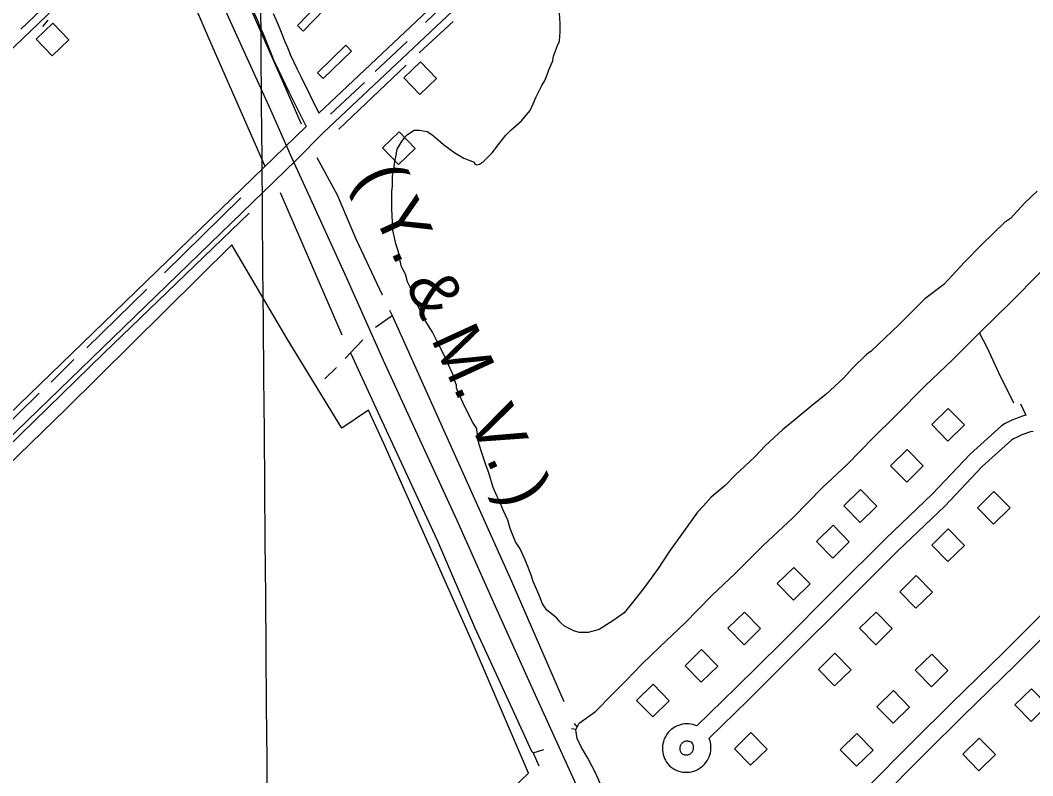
# Model space of a CAD drawing. Extents: x 3568792 to 3606828, y 529143 to 554785.
# Drawn here: x 3581187 to 3582938, y 537149 to 538456 of the extents above; entities that cross this region are included whole.
import ezdxf

# ---------------------------------------------------------------- set-up
doc = ezdxf.new("R2010")
doc.units = 0
for name, color, linetype in [('V-BLDG-OTLN', 7, 'Continuous'), ('V-DTCH-CNTR', 7, 'Continuous'), ('V-GRID-MAJR', 7, 'Continuous'), ('V-RAIL-IDEN', 7, 'Continuous'), ('V-RAIL-TRAK', 7, 'Continuous'), ('V-ROAD-CNTR', 7, 'Continuous'), ('V-SITE-VEGE', 7, 'Continuous'), ('V-TOPO-SHOR', 7, 'Continuous')]:
    doc.layers.add(name, color=color, linetype=linetype)

msp = doc.modelspace()

# ---------------------------------------------------------------- linework, layer by layer
at = {"layer": 'V-BLDG-OTLN'}
for points in [[(3581731, 538494.1), (3581720.9, 538503.9), (3581666.1, 538447.3), (3581676.1, 538437.5)], [(3581243.4, 538451.1), (3581214.4, 538423.5), (3581242.1, 538394.5), (3581271, 538422.1)], [(3581759.6, 538402.8), (3581749.9, 538412.9), (3581700.8, 538365.4), (3581710.5, 538355.3)], [(3581879.2, 538384.3), (3581850.4, 538356.6), (3581878.1, 538327.8), (3581906.9, 538355.5)], [(3581842.3, 538263), (3581813.4, 538235.3), (3581841.2, 538206.4), (3581870, 538234.2)], [(3582791.8, 537784.6), (3582763.2, 537756.6), (3582791.2, 537728), (3582819.8, 537756)], [(3582720.7, 537713.4), (3582692.1, 537685.4), (3582720.1, 537656.9), (3582748.7, 537684.9)], [(3582640.1, 537643.9), (3582611.5, 537615.9), (3582639.5, 537587.3), (3582668.1, 537615.3)], [(3582870.8, 537640.7), (3582842.3, 537612.7), (3582870.3, 537584.2), (3582898.8, 537612.2)], [(3582592.7, 537582.2), (3582564.1, 537554.2), (3582592.1, 537525.6), (3582620.7, 537553.6)], [(3582791.8, 537576), (3582763.2, 537548), (3582791.2, 537519.4), (3582819.8, 537547.4)], [(3582524.8, 537509.5), (3582496.2, 537481.5), (3582524.2, 537452.9), (3582552.8, 537480.9)], [(3582736.5, 537495.4), (3582707.9, 537467.4), (3582735.9, 537438.8), (3582764.5, 537466.8)], [(3582439.4, 537432.1), (3582410.9, 537404.1), (3582438.9, 537375.5), (3582467.4, 537403.5)], [(3582667, 537432.1), (3582638.4, 537404.1), (3582666.4, 537375.5), (3582695, 537403.5)], [(3582365.2, 537367.3), (3582336.6, 537339.3), (3582364.6, 537310.7), (3582393.2, 537338.7)], [(3582595.9, 537361), (3582567.3, 537333), (3582595.3, 537304.4), (3582623.9, 537332.4)], [(3582763.4, 537359.4), (3582734.8, 537331.4), (3582762.8, 537302.8), (3582791.4, 537330.8)], [(3582281.4, 537307.2), (3582252.8, 537279.2), (3582280.8, 537250.7), (3582309.4, 537278.7)], [(3582697, 537296.2), (3582668.4, 537268.2), (3582696.4, 537239.6), (3582725, 537267.6)], [(3582935.6, 537299.3), (3582907.1, 537271.3), (3582935.1, 537242.8), (3582963.6, 537270.8)], [(3582450.5, 537223.5), (3582421.9, 537195.5), (3582449.9, 537166.9), (3582478.5, 537194.9)], [(3582633.8, 537221.9), (3582605.2, 537193.9), (3582633.2, 537165.3), (3582661.8, 537193.3)], [(3582845.6, 537214), (3582817, 537186), (3582845, 537157.4), (3582873.6, 537185.4)]]:
    msp.add_lwpolyline(points, close=True, dxfattribs=at)
at = {"layer": 'V-DTCH-CNTR'}
for points in [[(3581743, 537750.6), (3581648.6, 537905.1), (3581552.6, 538067.7), (3581265.5, 537783.1), (3580939.5, 537466.5), (3580616.5, 537161.8), (3580274.6, 536830.3), (3580101.1, 536657.5), (3580153.1, 536594.7), (3580038.4, 536485.8), (3579962.5, 536549.1), (3579802, 536396.8), (3579619.1, 536225.5), (3579445.1, 536055.2), (3579345.4, 535955.3), (3579344.6, 535829.1)], [(3580720, 535828.9), (3580973.2, 536069.6), (3581210.5, 536310.3), (3581461.7, 536563.9), (3581688, 536784.7), (3581968.1, 537059.3), (3582065.8, 537153.2), (3581966.8, 537384.6), (3581815.9, 537723.7), (3581788.9, 537781.5), (3581743, 537750.6)]]:
    msp.add_lwpolyline(points, dxfattribs=at)
at = {"layer": 'V-GRID-MAJR'}
msp.add_spline([(3581635.7, 534620.4), (3581585.4, 540678.1), (3581535.2, 546738.9), (3581484.9, 552799.7), (3581484.9, 552802.8)], degree=3, dxfattribs=at)
at = {"layer": 'V-RAIL-TRAK'}
msp.add_lwpolyline([(3581410.4, 538763.3), (3581480.1, 538611.3), (3581541.1, 538473.8), (3581619.4, 538300.9), (3581656.8, 538217.8), (3581679.1, 538168.4), (3581751, 538010.4), (3581814.7, 537867.9), (3581883.5, 537717.3), (3581941.8, 537591), (3582005.6, 537448.5), (3582071.6, 537301.5), (3582148, 537134.5)], dxfattribs=at)
at = {"layer": 'V-ROAD-CNTR'}
msp.add_line((3580917.4, 537532.7), (3581681.3, 538272.3), dxfattribs=at)
for points in [[(3580938.2, 537511.2), (3581663.4, 538213.2), (3581711.4, 538262), (3582051.3, 538582.5), (3582436.7, 538953.5), (3582639.8, 539148.6), (3582821.3, 539321.6), (3582927.1, 539429.2)], [(3581703, 538295.3), (3582030.7, 538604.3), (3582415.9, 538975.1), (3582608.4, 539160.1)], [(3581303.8, 539100.6), (3581375.6, 538947), (3581461.2, 538756.9), (3581597, 538455.6)], [(3581328.7, 538556.4), (3581178.3, 538412), (3580914.7, 538160.5)], [(3581624.4, 538467.7), (3581629.4, 538456.1), (3581634.4, 538444.4), (3581639.3, 538432.6), (3581644.1, 538420.8), (3581648.9, 538409), (3581653.5, 538397.3)], [(3581596.9, 538455.8), (3581601.9, 538444.3), (3581606.8, 538432.7), (3581611.6, 538421.2), (3581616.3, 538409.6), (3581621, 538397.9), (3581625.6, 538386.3)], [(3581653.1, 538398.2), (3581659.3, 538385), (3581665.6, 538371.8), (3581671.9, 538358.7), (3581703, 538295.3)], [(3581626, 538385.4), (3581632.2, 538372.1), (3581638.6, 538358.9), (3581645, 538345.6), (3581651.4, 538332.4), (3581681.3, 538272.3)], [(3582916.7, 537792.7), (3582925.8, 537772.7)], [(3582925.9, 537772.6), (3582920.1, 537770.9), (3582914, 537768.8), (3582908, 537766.5), (3582902.1, 537764), (3582896.3, 537761.3), (3582890.6, 537758.3), (3582883.9, 537754.5), (3582829.6, 537705.2), (3582764.7, 537636.6), (3582683.8, 537559.6), (3582595, 537471), (3582503.2, 537379.1), (3582424.5, 537300.8), (3582357.2, 537235.3)], [(3582938.5, 537744.8), (3582934.1, 537743.7), (3582929.1, 537742.2), (3582924.1, 537740.6), (3582919.2, 537738.7), (3582914.4, 537736.7), (3582909.7, 537734.4), (3582905, 537732), (3582901.6, 537730.1), (3582850.6, 537683.7), (3582786, 537615.4), (3582704.8, 537538.1), (3582616.2, 537449.8), (3582524.3, 537357.9), (3582445.6, 537279.4), (3582378.2, 537214)], [(3582648.6, 537125.7), (3582730.9, 537208.4), (3582797.3, 537274.5), (3582886.7, 537361.4), (3582977.8, 537452.8), (3582990.9, 537466), (3582995.3, 537469.8), (3582999.8, 537473.2), (3583004.4, 537476.5), (3583009.1, 537479.5), (3583014, 537482.2), (3583019.1, 537484.7), (3583024.2, 537487), (3583029.4, 537489), (3583051, 537496.2)], [(3582669.9, 537104.6), (3582752.1, 537187.2), (3582818.4, 537253.2), (3582907.8, 537340), (3582999, 537431.6), (3583011.4, 537444), (3583014.4, 537446.6), (3583017.6, 537449.1), (3583021, 537451.5), (3583024.5, 537453.7), (3583028.1, 537455.7), (3583031.8, 537457.6), (3583035.6, 537459.2), (3583039.5, 537460.7), (3583063.3, 537468.7)], [(3582357.2, 537235.3), (3582353.8, 537236.6), (3582350.3, 537237.6), (3582346.7, 537238.3), (3582343.1, 537238.7), (3582339.4, 537238.8), (3582335.8, 537238.6), (3582332.2, 537238), (3582328.6, 537237.2), (3582325.2, 537236), (3582321.8, 537234.6), (3582318.6, 537232.9), (3582315.5, 537230.9), (3582312.6, 537228.7), (3582309.9, 537226.2), (3582307.5, 537223.5), (3582305.3, 537220.6), (3582303.3, 537217.5), (3582301.6, 537214.3), (3582300.2, 537210.9), (3582299.1, 537207.4), (3582298.2, 537203.9), (3582297.7, 537200.3), (3582297.5, 537196.6), (3582297.6, 537193), (3582298, 537189.3), (3582298.7, 537185.8), (3582299.8, 537182.3), (3582301.1, 537178.9), (3582302.7, 537175.6), (3582304.6, 537172.4), (3582306.7, 537169.5), (3582309.5, 537166.2), (3582312.9, 537163.5), (3582316, 537161.4), (3582319.2, 537159.5), (3582322.6, 537158), (3582326.1, 537156.7), (3582329.7, 537155.8), (3582333.3, 537155.2), (3582337.1, 537154.9), (3582340.8, 537154.9), (3582344.5, 537155.3), (3582348.1, 537155.9), (3582351.7, 537156.9), (3582355.2, 537158.2), (3582358.6, 537159.8), (3582361.8, 537161.7), (3582364.8, 537163.8), (3582367.7, 537166.2), (3582370.3, 537168.9), (3582372.7, 537171.7), (3582374.8, 537174.8), (3582376.6, 537178), (3582378.2, 537181.4), (3582379.5, 537184.8), (3582380.4, 537188.4), (3582381.1, 537192.1), (3582381.4, 537195.8), (3582381.4, 537199.5), (3582381.1, 537203.2), (3582380.4, 537206.9), (3582379.5, 537210.5), (3582378.2, 537214)], [(3582349.5, 537205), (3582348.2, 537206.1), (3582347.3, 537206.7), (3582346.3, 537207.3), (3582345.4, 537207.8), (3582344.3, 537208.1), (3582343.3, 537208.4), (3582342.2, 537208.6), (3582341.1, 537208.8), (3582340.1, 537208.8), (3582339, 537208.7), (3582337.9, 537208.6), (3582336.8, 537208.3), (3582335.8, 537208), (3582334.8, 537207.5), (3582333.8, 537207), (3582332.9, 537206.4), (3582332, 537205.8), (3582331.2, 537205), (3582330.5, 537204.2), (3582329.8, 537203.4), (3582329.3, 537202.4), (3582328.8, 537201.5), (3582328.3, 537200.5), (3582328, 537199.4), (3582327.7, 537198.4), (3582327.6, 537197.3), (3582327.5, 537196.2), (3582327.6, 537195.1), (3582327.7, 537194), (3582327.9, 537193), (3582328.2, 537191.9), (3582328.6, 537190.9), (3582329.1, 537189.9), (3582329.6, 537189), (3582330.3, 537188.1), (3582330.6, 537187.8), (3582330.9, 537187.5), (3582331.8, 537186.8), (3582332.8, 537186.3), (3582333.8, 537185.8), (3582334.9, 537185.5), (3582336, 537185.2), (3582337, 537185), (3582338.2, 537184.9), (3582339.3, 537184.9), (3582340.4, 537185), (3582341.5, 537185.2), (3582342.5, 537185.5), (3582343.6, 537185.9), (3582344.6, 537186.4), (3582345.5, 537186.9), (3582346.4, 537187.6), (3582347.3, 537188.3), (3582348.1, 537189.1), (3582348.8, 537189.9), (3582349.4, 537190.8), (3582350, 537191.8), (3582350.4, 537192.8), (3582350.8, 537193.9), (3582351.1, 537194.9), (3582351.3, 537196), (3582351.4, 537197.1), (3582351.4, 537198.2), (3582351.3, 537199.3), (3582351.1, 537200.4), (3582350.8, 537201.5), (3582350.5, 537202.6), (3582350, 537203.6), (3582349.4, 537204.5), (3582348.8, 537205.4), (3582347.7, 537206.8)]]:
    msp.add_lwpolyline(points, dxfattribs=at)
at = {"layer": 'V-SITE-VEGE'}
for points in [[(3581980.1, 537723.8), (3581976.7, 537747.6), (3581976.7, 537749.8), (3581969.9, 537760), (3581954, 537790.6), (3581948.4, 537804.2), (3581942.7, 537816.6), (3581941.6, 537820), (3581941.6, 537824.6), (3581938.2, 537832.5), (3581934.8, 537843.8), (3581925.7, 537863.1), (3581919, 537878.9), (3581907.6, 537901.6), (3581899.7, 537916.3), (3581887.3, 537936.7), (3581871.4, 537968.4), (3581868, 537978.6), (3581861.2, 537994.4), (3581856.7, 538003.5), (3581853.3, 538017), (3581846.5, 538029.5), (3581842, 538047.6), (3581840.9, 538055.5), (3581836.3, 538069.1), (3581834.1, 538080.5), (3581830.7, 538095.2), (3581830.7, 538106.5), (3581829.5, 538129.1), (3581829.5, 538159.7), (3581830.7, 538169.9), (3581830.7, 538186.9), (3581832.9, 538195.9), (3581834.1, 538208.4), (3581836.3, 538219.7), (3581838.6, 538233.3), (3581845.4, 538244.6), (3581852.2, 538253.7), (3581856.7, 538258.2), (3581868.1, 538266.1), (3581877.1, 538266.1), (3581890.7, 538263.9), (3581898.6, 538258.2), (3581909.9, 538249.1), (3581919, 538241.2), (3581938.2, 538226.5), (3581954.1, 538217.4), (3581972.2, 538210.6), (3581973.3, 538207.2), (3581976.7, 538206.1), (3581981.3, 538207.2), (3581988.1, 538211.8), (3582002.8, 538226.5), (3582014.1, 538241.2), (3582026.6, 538257.1), (3582035.6, 538266.1), (3582053.7, 538282), (3582061.7, 538292.2), (3582068.5, 538300.1), (3582074.1, 538311.4), (3582078.7, 538322.7), (3582088.8, 538343.1), (3582093.4, 538351), (3582096.8, 538359), (3582101.3, 538370.3), (3582108.1, 538386.1), (3582109.2, 538394), (3582116, 538412.2), (3582119.4, 538420.1), (3582120.6, 538435.9), (3582120.6, 538450.7), (3582119.4, 538468.8)], [(3582945.9, 538160.7), (3582924.4, 538140.3), (3582899.5, 538113.2), (3582889.3, 538106.4), (3582849.7, 538067.9), (3582820.2, 538037.3), (3582784, 537998.8), (3582751.2, 537973.9), (3582707, 537929.8), (3582658.3, 537883.3), (3582650.4, 537877.7), (3582626.6, 537855), (3582610.7, 537836.9), (3582580.2, 537808.6), (3582557.5, 537790.5), (3582526.9, 537765.6), (3582505.4, 537747.5), (3582476, 537720.3), (3582456.7, 537699.9), (3582423.9, 537669.4), (3582405.8, 537651.3), (3582382, 537630.9), (3582368.4, 537616.2), (3582358.2, 537604.9), (3582308.4, 537535.8), (3582290.3, 537507.5), (3582265.4, 537473.5), (3582250.6, 537454.3), (3582231.4, 537430.5), (3582213.3, 537418.1), (3582188.4, 537402.2), (3582169.1, 537396.5), (3582153.3, 537396.6), (3582144.2, 537399.9), (3582128.4, 537407.9), (3582120.4, 537414.7), (3582114.8, 537421.5), (3582108, 537427.1), (3582097.8, 537435.1), (3582089.9, 537446.4), (3582084.2, 537461.1), (3582074, 537484.9), (3582070.6, 537496.2), (3582065, 537510.9), (3582060.4, 537522.2), (3582051.4, 537541.5), (3582043.5, 537553.9), (3582034.4, 537576.6), (3582029.9, 537591.3), (3582022, 537608.3), (3582016.3, 537623), (3582011.8, 537632.1), (3582005, 537647.9), (3581997.1, 537672.8), (3581992.5, 537685.3), (3581985.7, 537705.7), (3581980.1, 537723.8)]]:
    msp.add_lwpolyline(points, dxfattribs=at)
at = {"layer": 'V-TOPO-SHOR'}
for p, q in [((3581187.8, 538441), (3581255.7, 538505.7)), ((3581945.4, 538508.3), (3581888, 538452.3)), ((3581225.9, 538445.1), (3581235.4, 538456.1)), ((3581876.6, 538399.9), (3581935.4, 538454.1)), ((3581856.1, 538419.5), (3581800.5, 538367.6)), ((3581737.7, 538267.9), (3581854.3, 538378.5)), ((3581782.3, 538348.5), (3581723.5, 538293.8)), ((3581436.4, 538018.9), (3581568.4, 538148.6)), ((3581743.4, 537911.1), (3581636.7, 538157.8)), ((3581302, 537889.6), (3581405.6, 537990.9)), ((3581801.5, 537925.2), (3581830, 537945.2)), ((3581240.1, 537830), (3581279.5, 537869)), ((3581713.5, 537835.4), (3581733.7, 537855.1)), ((3582144.7, 537239.2), (3582150, 537232.9)), ((3582140.5, 537230.4), (3582148.3, 537229.5)), ((3582074.1, 537188.3), (3582083.8, 537165.9))]:
    msp.add_line(p, q, dxfattribs=at)
for points in [[(3581317.4, 539072.2), (3581339, 539024.4), (3581374, 538947.2), (3581427.7, 538828.1), (3581455.5, 538764.3), (3581479.2, 538709.9), (3581527, 538609.6), (3581531.4, 538599.7), (3581576.6, 538496.5), (3581634.1, 538365), (3581672.7, 538277.2)], [(3581610.7, 538202.9), (3581516.3, 538417), (3581455.3, 538559.4)], [(3581699.8, 538218.8), (3581734.7, 538154), (3581767.4, 538078.1), (3581812.9, 537981.1)], [(3580510, 537087.1), (3580799.8, 537368.5), (3581064.9, 537620.6), (3581331.3, 537880), (3581582.5, 538122.1)], [(3582201.7, 537107.6), (3582182.4, 537152.5), (3582168.3, 537179.5), (3582157.6, 537197.8), (3582150, 537213.6), (3582147.9, 537228.6), (3582153.6, 537240), (3582181.5, 537260), (3582211.1, 537289.8), (3582235.1, 537313.4), (3582261.6, 537341.3), (3582293.2, 537372.2), (3582336, 537412.9), (3582382.9, 537460.9), (3582423.3, 537498.8), (3582471.4, 537546.8), (3582523.4, 537595.9), (3582574.2, 537647.4), (3582617, 537687.7), (3582661.9, 537733.4), (3582700.3, 537771.3), (3582752.4, 537824), (3582799.2, 537868.4), (3582846.1, 537915.3), (3582899.7, 537967.5), (3582951, 538019.4)], [(3581825.7, 537954.7), (3581830, 537945.2), (3582036.7, 537485.7), (3582127.2, 537277.4)], [(3582905.5, 537793.5), (3582879.4, 537846), (3582859.5, 537889), (3582846.1, 537915.3)], [(3581748.8, 537871.1), (3581757.8, 537880.6), (3581779.5, 537903.2)], [(3581757.8, 537880.6), (3581808.7, 537770.6), (3581908.2, 537556.4), (3581972.3, 537406.1), (3582037.9, 537264.4), (3582071.3, 537191.5), (3582074.1, 537188.3), (3582092.4, 537194.2)], [(3581059.7, 537654.8), (3581112.1, 537705.9), (3581219.7, 537811.1)]]:
    msp.add_lwpolyline(points, dxfattribs=at)

# ---------------------------------------------------------------- texts
at = {"layer": 'V-RAIL-IDEN'}
msp.add_text('( Y. & M. V. )', height=83, rotation=294.6769, dxfattribs=at).set_placement((3581767.6, 538185.5))

doc.saveas('drawing.dxf')
